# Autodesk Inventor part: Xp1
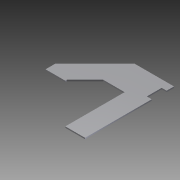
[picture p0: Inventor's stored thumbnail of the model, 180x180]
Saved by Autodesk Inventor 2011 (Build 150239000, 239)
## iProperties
Created: 2014-11
Part Number: Xp1
Document SubType Name: Modeling
Designer: Evgeny
Density: 1 g/cm^3
Author: Evgeny
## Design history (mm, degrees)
sketch "Эскиз1"
  geometry: L1 (0, 0)-(-8, 0); L2 (-8, 0)-(-8, 24); L3 (-8, 24)-(-16.686, 24); L4 (-16.686, 24)-(-24, 16.686); L5 (-24, 16.686)-(-24, 16); L6 (-24, 16)-(-32, 16); L7 (-32, 16)-(-32, 20); L8 (-32, 20)-(-16, 36); L9 (-16, 36)-(0, 36); L10 (0, 33)-(-2, 33); L11 (-2, 33)-(-2, 27); L12 (-2, 27)-(0, 27); L13 (0, 36)-(0, 33); L14 (0, 27)-(0, 0)
  constraints: 28 end point, 8 parallel, 6 perpendicular, 1 collinear, 1 horizontal
  dimensions: "d0" = 36 distance between parallel lines of L9 L1; "d2" = 12 distance between parallel lines of L3 L9; "d3" = 8 distance between parallel lines of L8 L4; "d4" = 16 distance of L8.end L9.end; "d5" = 135 deg angle of L9 L8; "d6" = 8 distance between parallel lines of L7 L5; "d7" = 16 distance between parallel lines of L2 L5; "d8" = 16 distance between parallel lines of L6 L1; "d31" = 6 distance between parallel lines of L12 L10; "d32" = 3 distance between parallel lines of L9 L10; "d33" = 2 distance between parallel lines of L11 L13; "d34" = 8 distance between parallel lines of L2 L14
extrude "Выдавливание1" new body sketch "Эскиз1" distance "d9" = 0.5; taper "d10" = 0 deg
node "Твердое тело1"
other parameters: "d1" = 8, "d11" = 32 (derived)
